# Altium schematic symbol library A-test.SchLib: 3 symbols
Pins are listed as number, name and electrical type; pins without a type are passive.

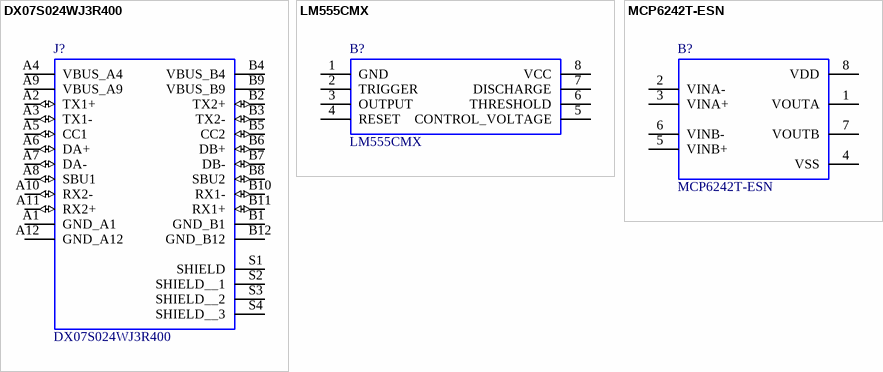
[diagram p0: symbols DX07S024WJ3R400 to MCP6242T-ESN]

## DX07S024WJ3R400
designator J?
______________________________________________________USB-C_(USB_TYPE-C)_USB_3.2_Gen_2_(USB_3.1_Gen_2,_Superspeed_+_(USB_3.1))_Receptacle_Connector_24_Position_Surface_Mount,_Through_Hole______________________________________________; MF: JAE_Electronics; PKG_TYPE: JAE_DX07S024WJ3R400
footprint JAE_DX07S024WJ3R400
pins: A1 GND_A1, A2 TX1+ (io), A3 TX1- (io), A4 VBUS_A4 (power), A5 CC1 (io), A6 DA+ (io), A7 DA- (io), A8 SBU1 (io), A9 VBUS_A9 (power), A10 RX2- (io), A11 RX2+ (io), A12 GND_A12, B1 GND_B1, B2 TX2+ (io), B3 TX2- (io), B4 VBUS_B4 (power), B5 CC2 (io), B6 DB+ (io), B7 DB- (io), B8 SBU2 (io), B9 VBUS_B9 (power), B10 RX1- (io), B11 RX1+ (io), B12 GND_B12, S1 SHIELD, S2 SHIELD__1, S3 SHIELD__2, S4 SHIELD__3

## LM555CMX
designator B?
Obsolete - Single Timer; Manufacturer_Name: onsemi; Geometry.Height: 1.75mm
footprint SOIC127P600X175-8N
pins: 1 GND, 2 TRIGGER, 3 OUTPUT, 4 RESET, 5 CONTROL_VOLTAGE, 6 THRESHOLD, 7 DISCHARGE, 8 VCC

## MCP6242T-ESN
designator B?
______________________________________________________???1.8V,_550kHz_OP,_E_?⑤룄_¦_Microchip_Technology_Inc._MCP6242T-E/SN______________________________________________; E2_MAX: 0.0; E1_MIN: 3.9; B_NOM: 0.41; B_MAX: 0.51; ENOM: 1.27; D_NOM: 4.9; A_MAX: 1.75; E_NOM: 6.0; B_MIN: 0.31; PIN_COUNT: 8.0; L_NOM: 0.835; A1_MIN: 0.175; L_MIN: 0.4; PKG_TYPE: SOIC127P600X175-8N
footprint SOIC127P600X175-8N
pins: 1 VOUTA, 2 VINA-, 3 VINA+, 4 VSS, 5 VINB+, 6 VINB-, 7 VOUTB, 8 VDD (power)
